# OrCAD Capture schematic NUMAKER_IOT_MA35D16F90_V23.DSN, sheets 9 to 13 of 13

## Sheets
9 03. PowerOn_SWJ(VDDIO1): size B; note: 03. Power On Setting (VDDIO1); block SCHEMATIC03
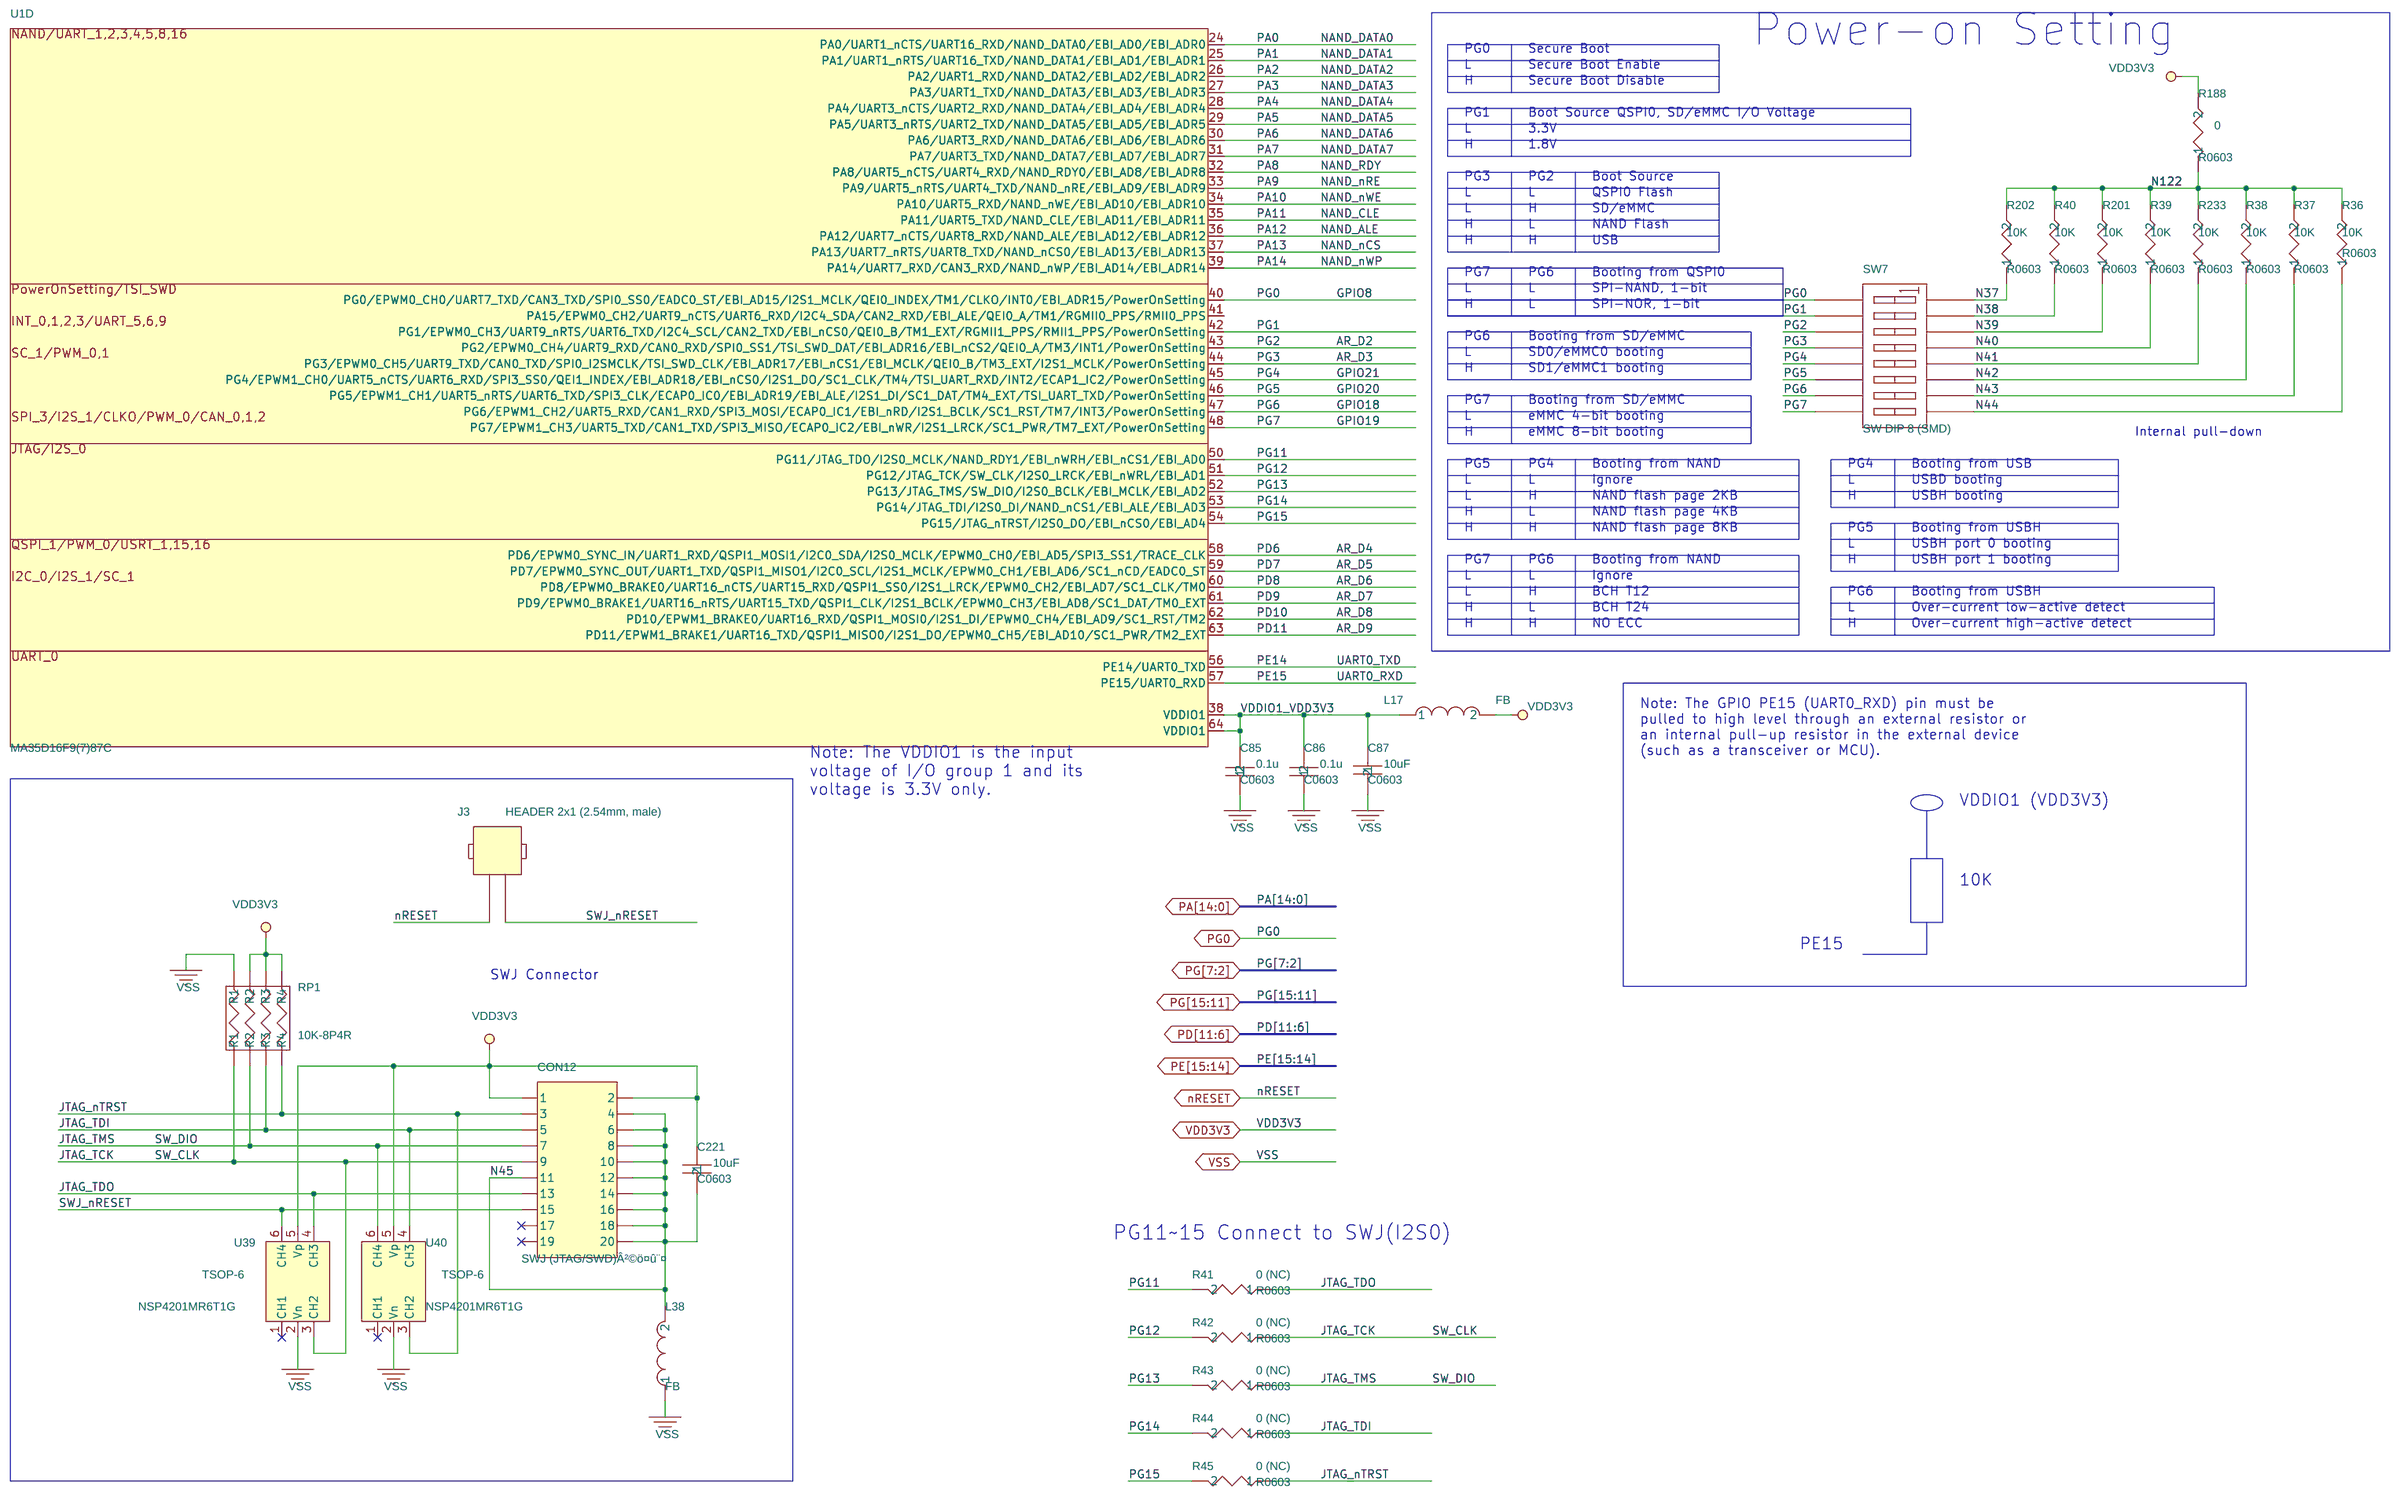
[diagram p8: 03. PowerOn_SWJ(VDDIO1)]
10 04. CCAP0 (VDDIO2): size B; note: 04. CCAP0 (VDDIO2); block SCHEMATIC04
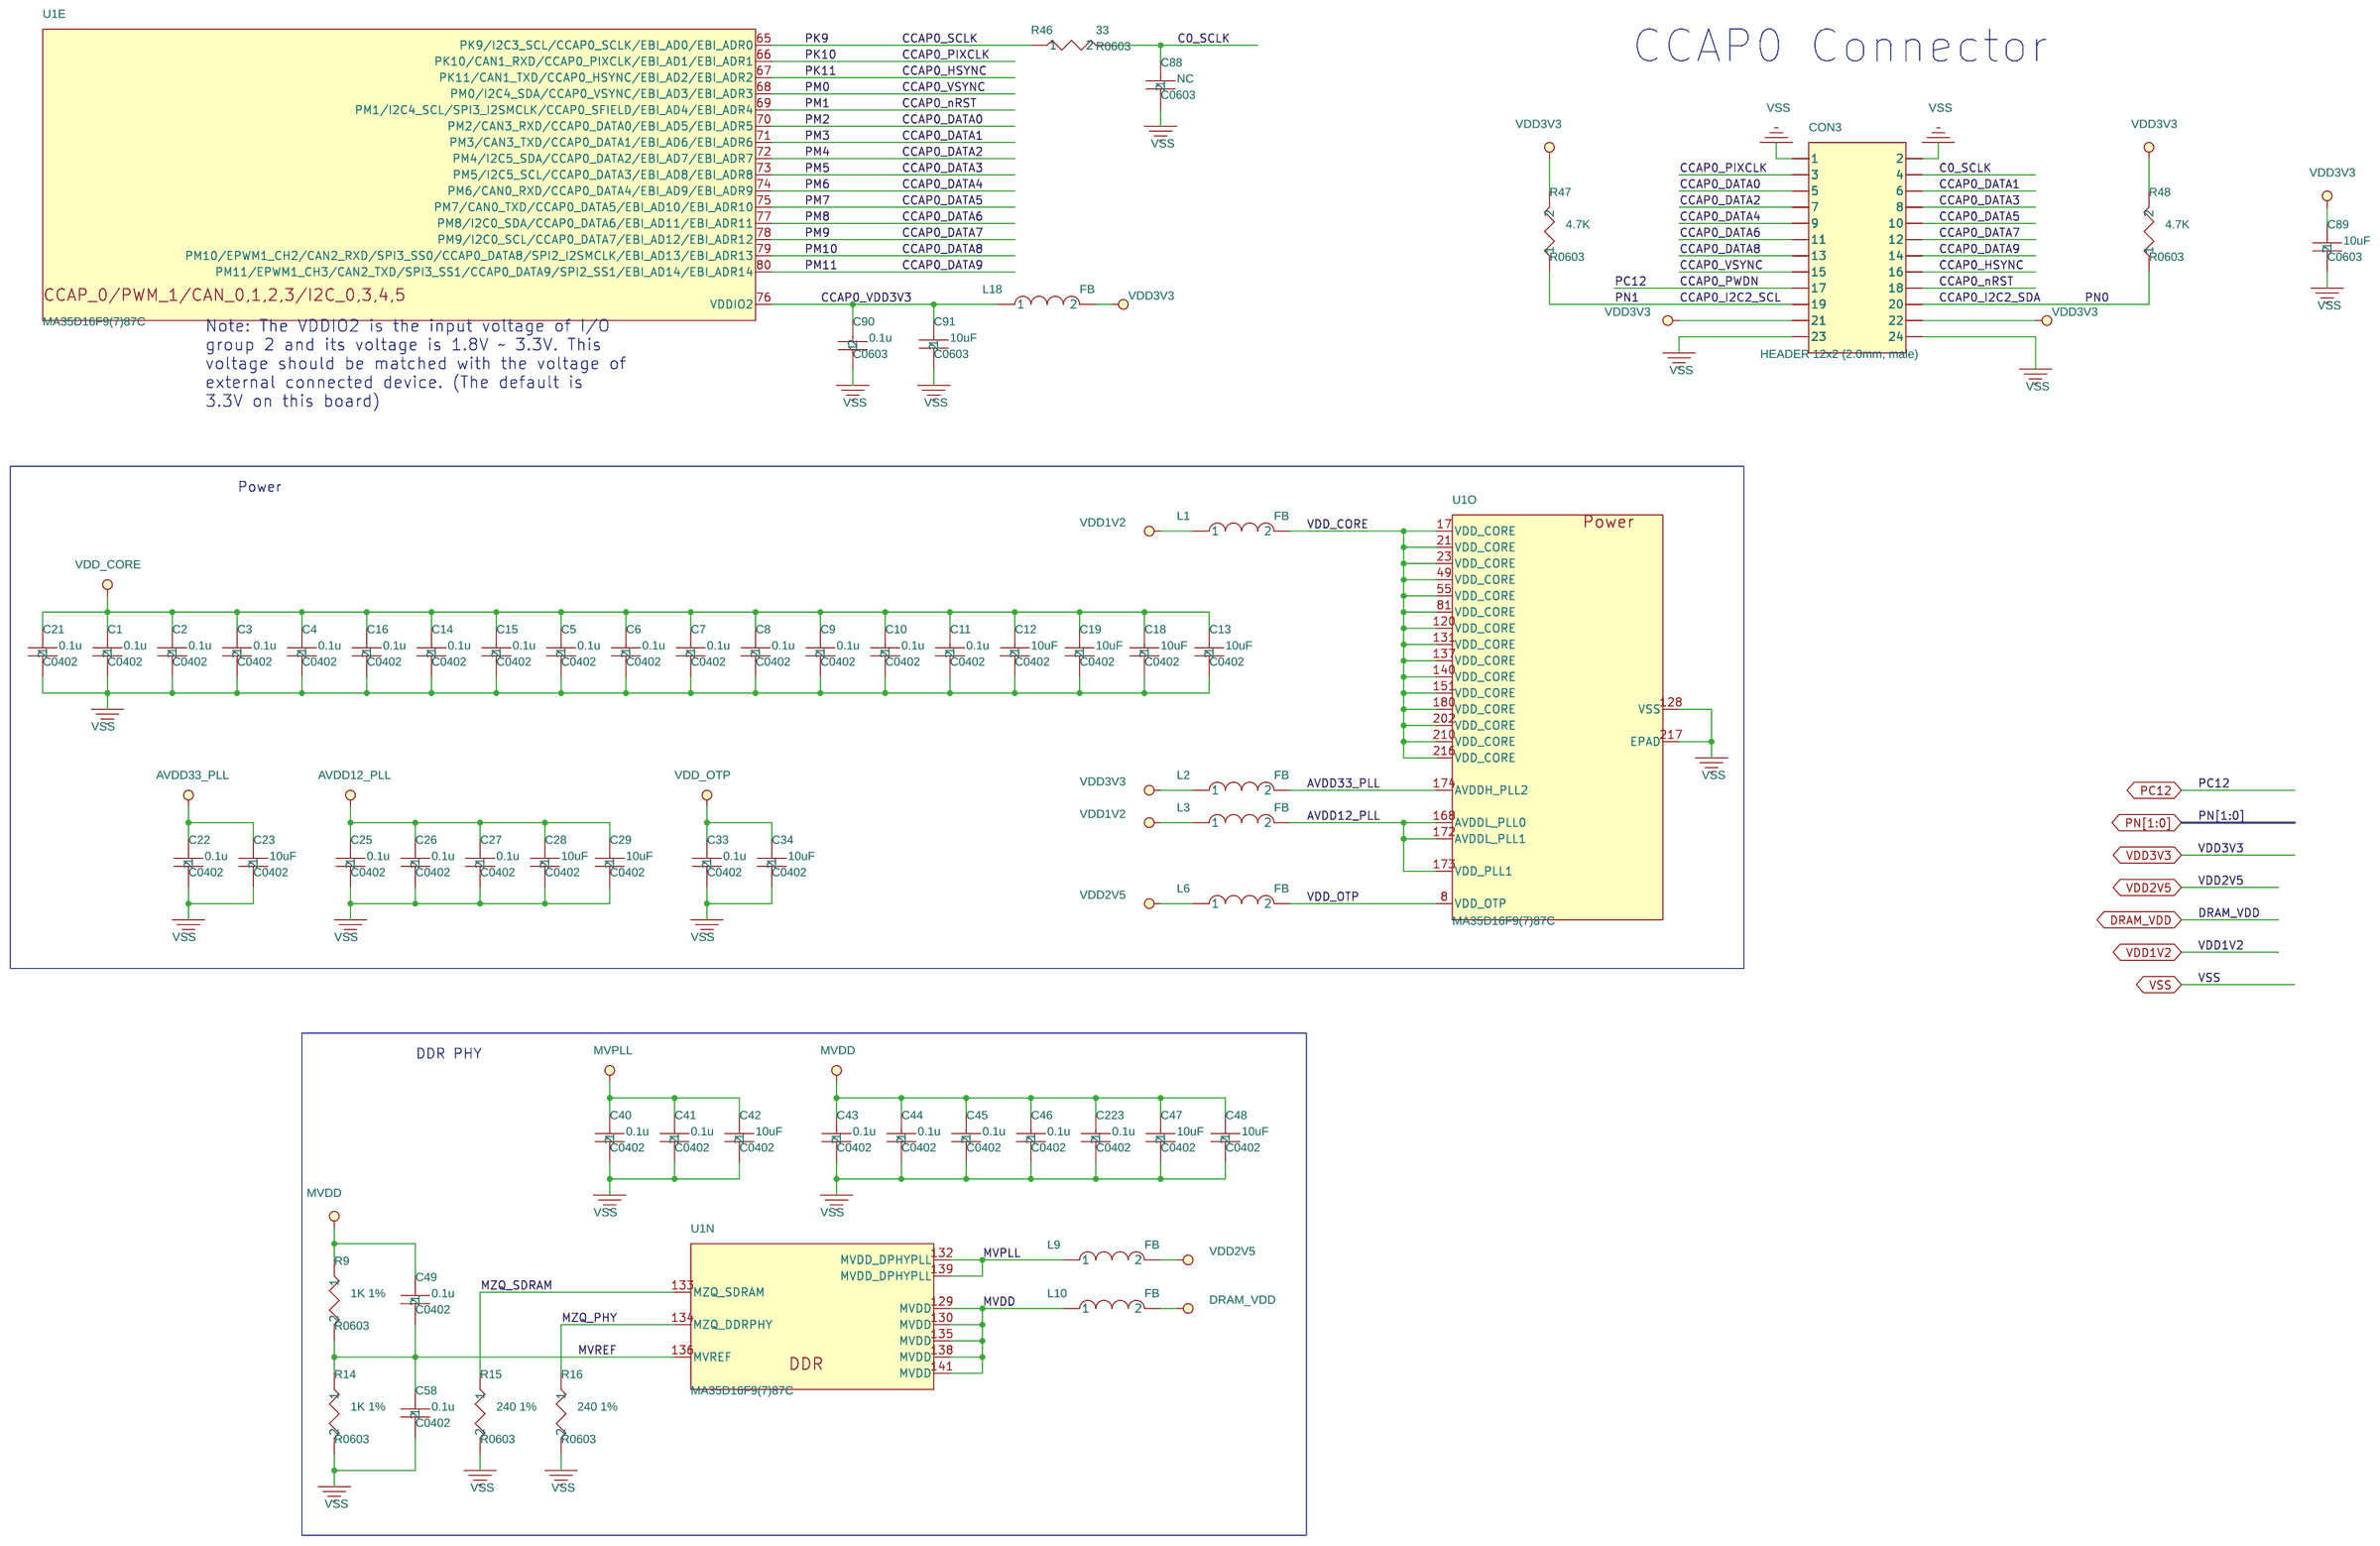
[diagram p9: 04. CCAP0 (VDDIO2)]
11 05. RP PI (VDDIO4): size B; note: 05. RP PI (VDDIO4); block SCHEMATIC05
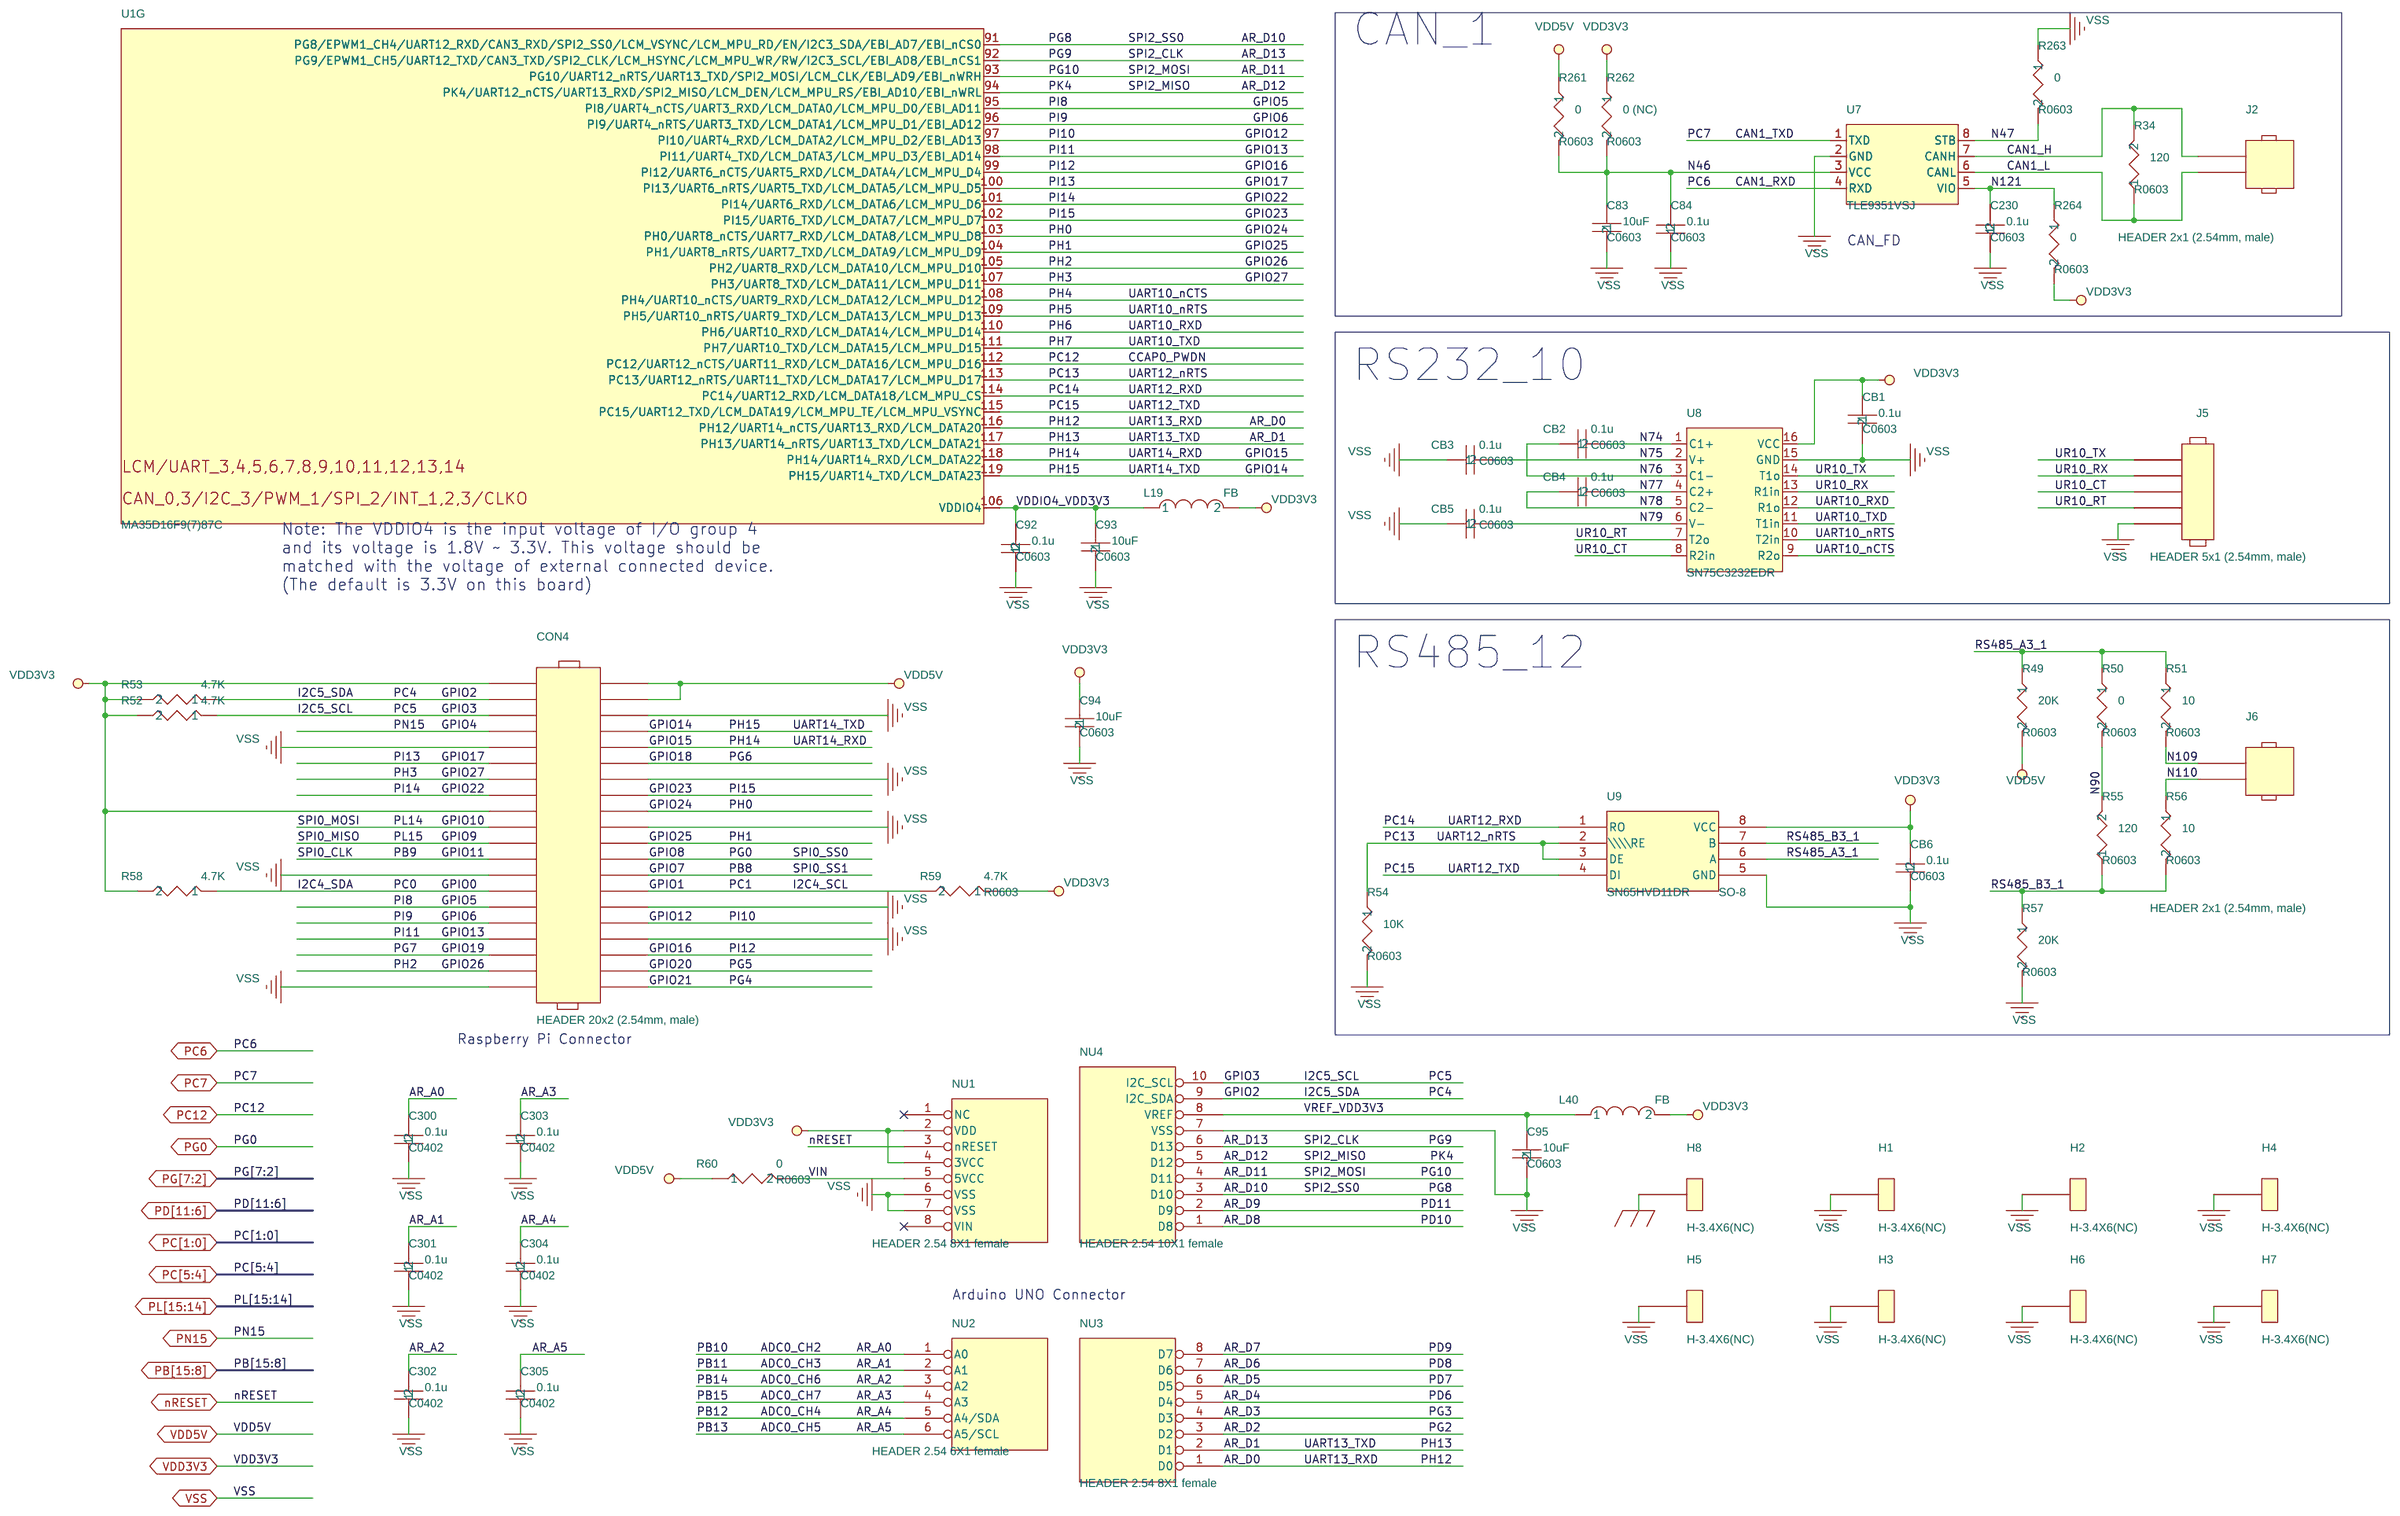
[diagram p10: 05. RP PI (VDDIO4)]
12 06. NAND/QSPI0 (VDDIO5): size B; note: 06. NAND/QSPI0 (VDDIO5); block SCHEMATIC06
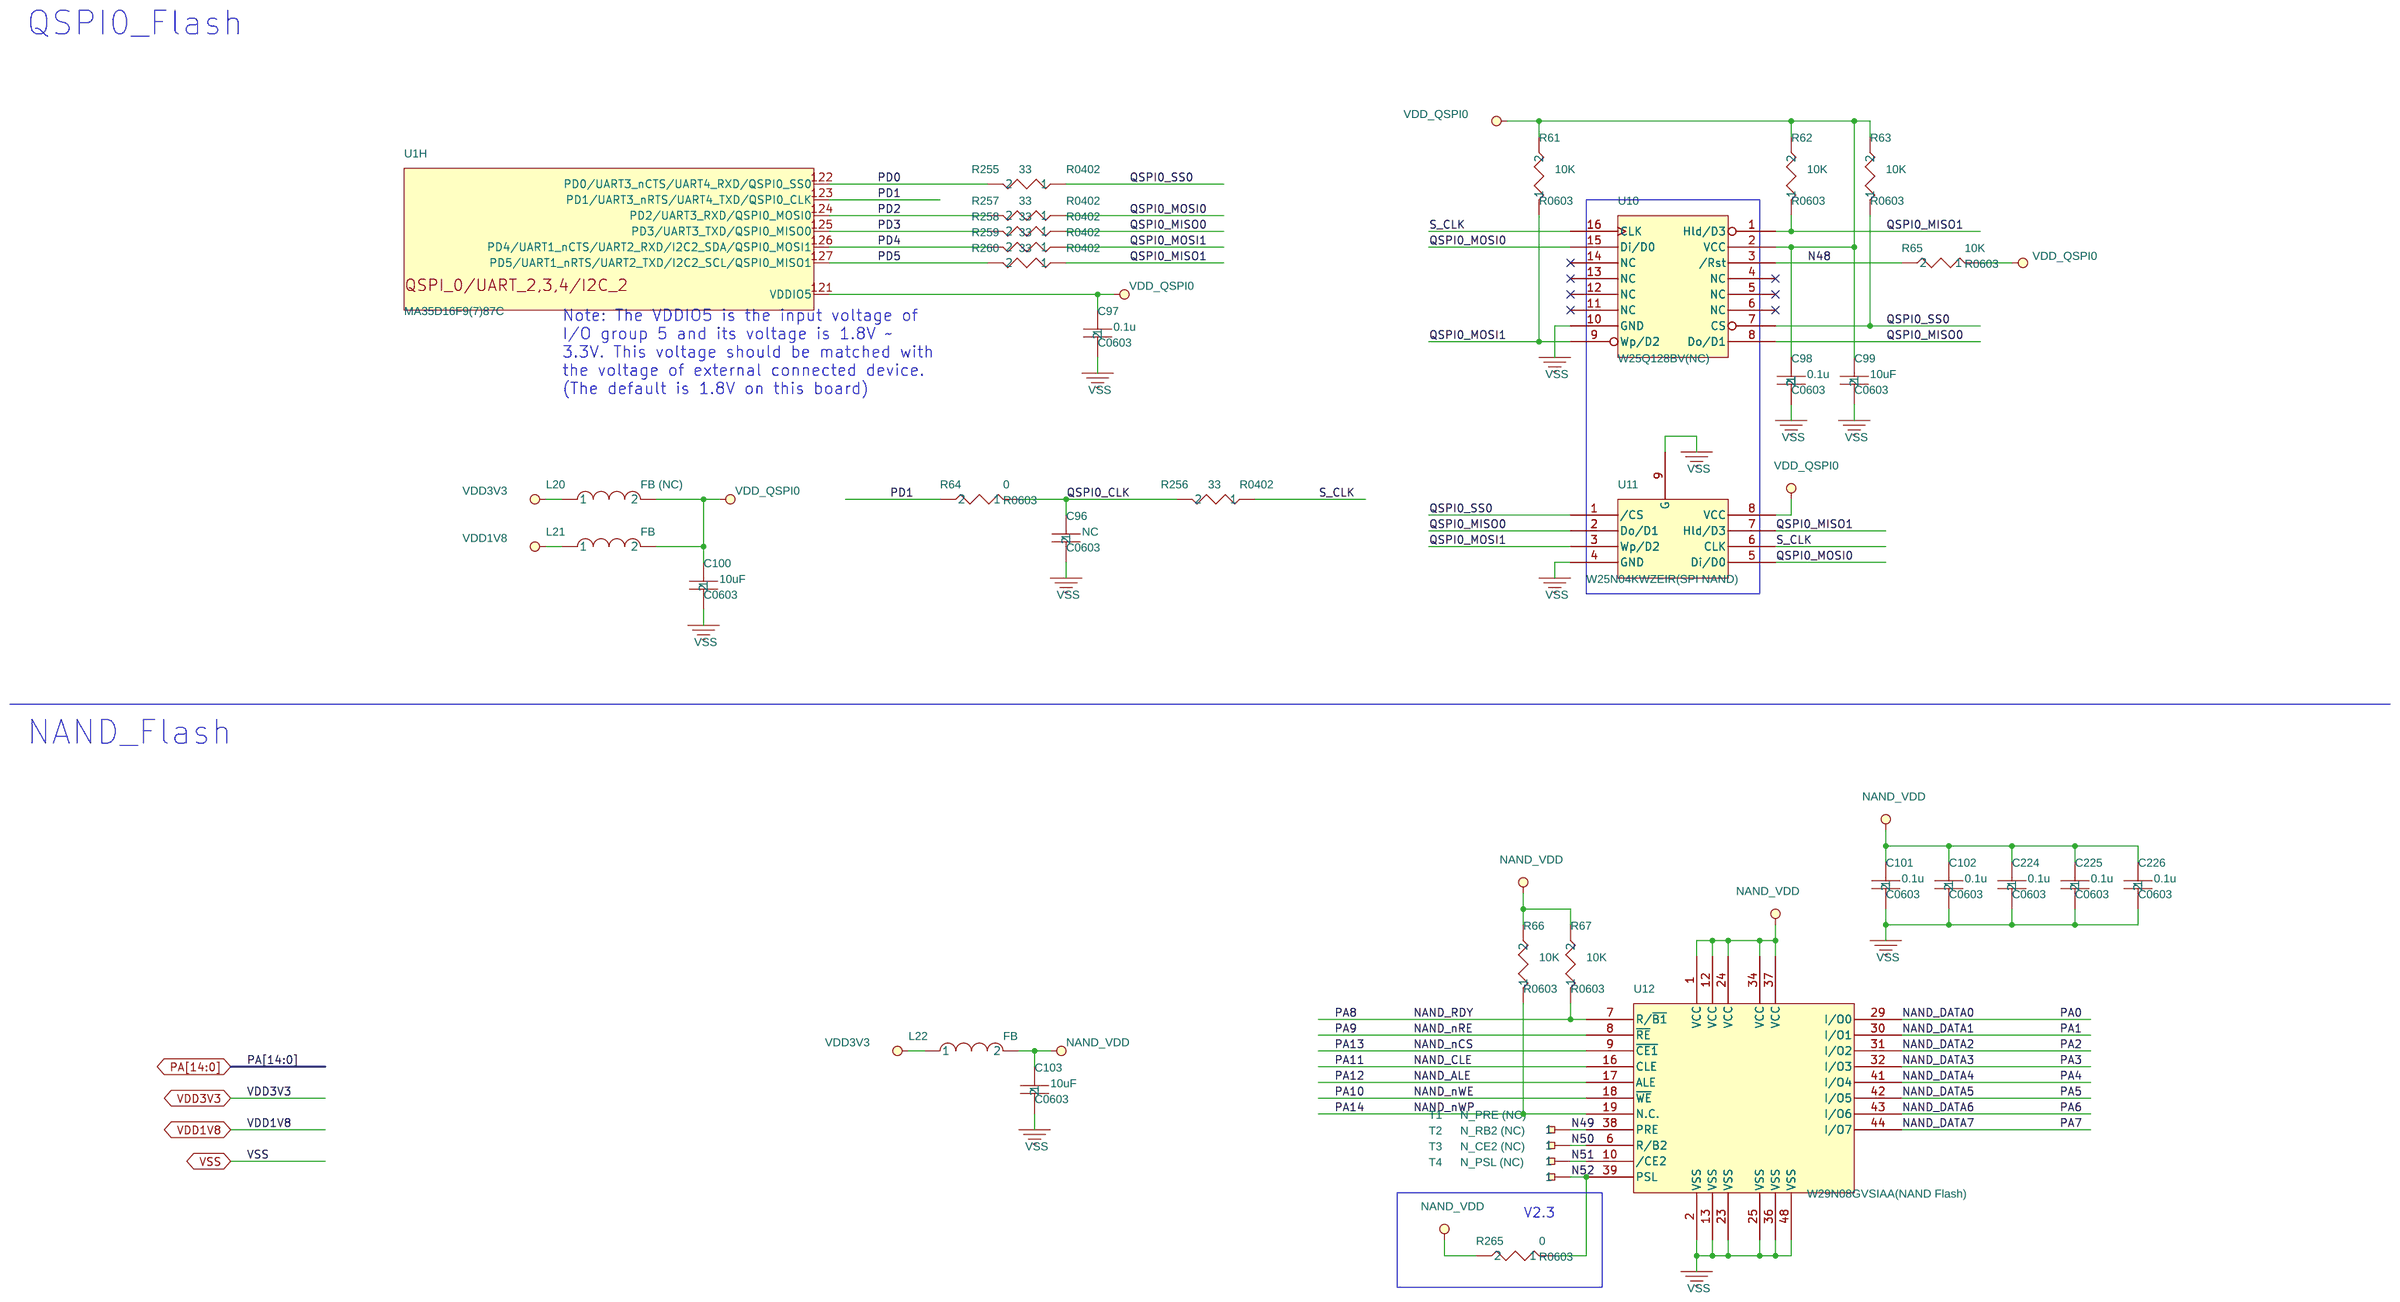
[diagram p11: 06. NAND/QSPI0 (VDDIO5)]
13 07. SD1 (VDDIO3): size B; note: 07. SD1 (VDDIO3); block SCHEMATIC07
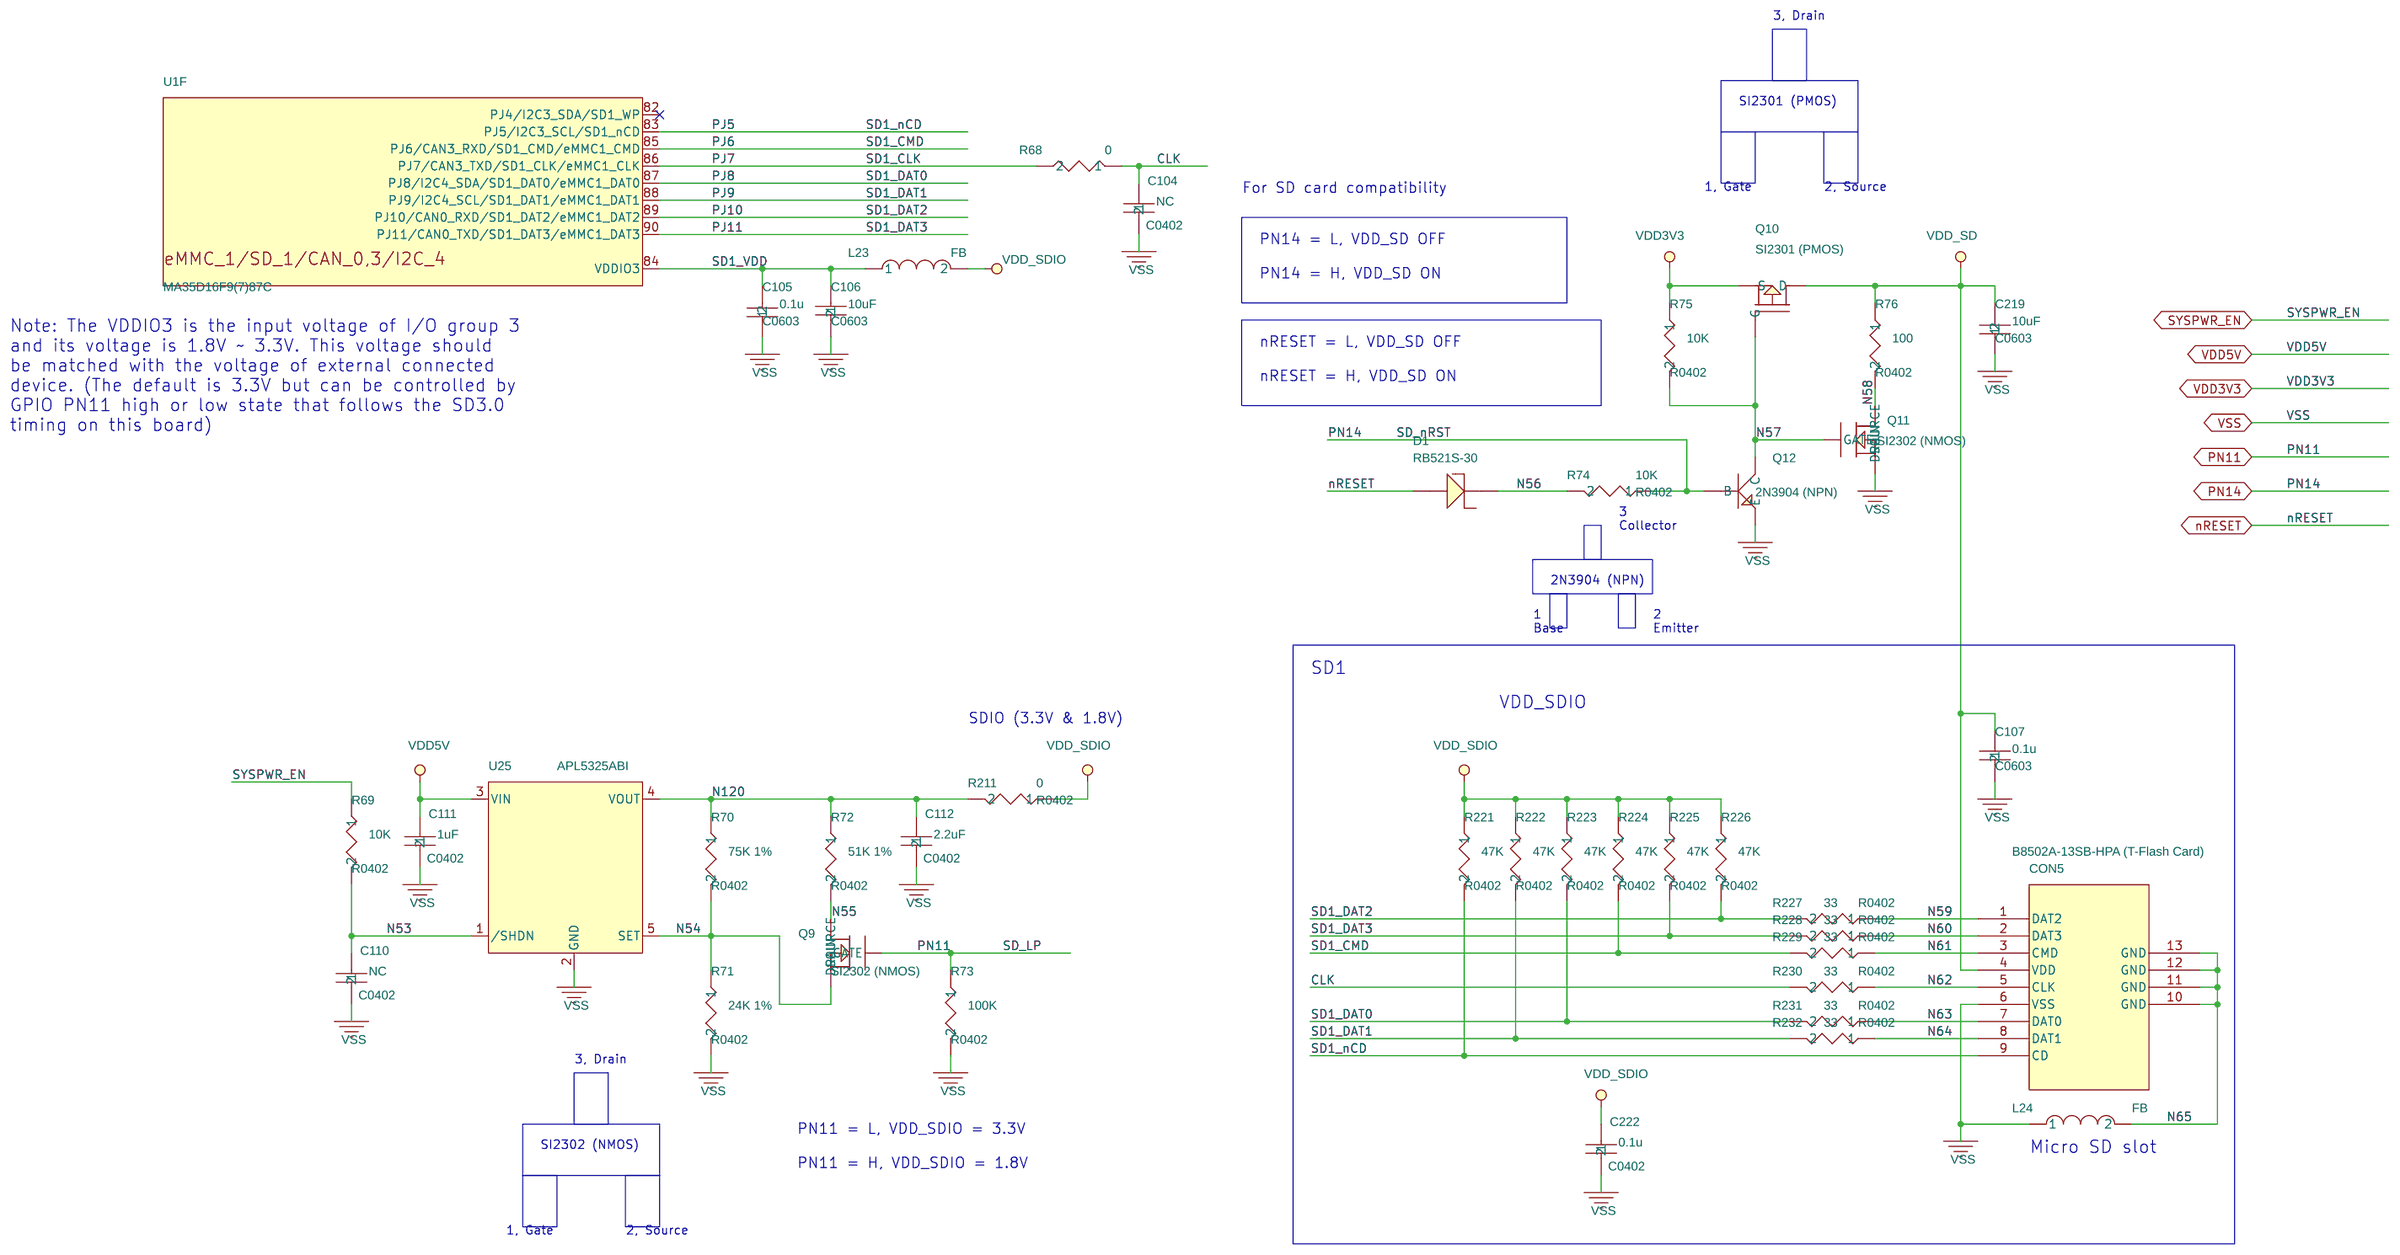
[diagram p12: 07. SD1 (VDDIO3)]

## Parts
sheet 03. PowerOn_SWJ(VDDIO1)
C85  0.1u  [C0603]
C86  0.1u  [C0603]
C87  10uF  [C0603]
C221  10uF  [C0603]
CON12  SWJ (JTAG/SWD)Â²©ö¤û¨¤  [HEADER10X2\BOX]
J3  HEADER 2x1 (2.54mm, male)  [HEADER2x1]
L17  FB  [L0603]
L38  FB  [L0603]
R36  10K  [R0603]
R37  10K  [R0603]
R38  10K  [R0603]
R39  10K  [R0603]
R40  10K  [R0603]
R41  0 (NC)  [R0603]
R42  0 (NC)  [R0603]
R43  0 (NC)  [R0603]
R44  0 (NC)  [R0603]
R45  0 (NC)  [R0603]
R188  0  [R0603]
R201  10K  [R0603]
R202  10K  [R0603]
R233  10K  [R0603]
RP1  10K-8P4R  [8P4RA]
SW7  SW DIP 8 (SMD)  [SWDIP-8/SMD]
U39  NSP4201MR6T1G  [TSOP-6]
U40  NSP4201MR6T1G  [TSOP-6]
sheet 04. CCAP0 (VDDIO2)
C1  0.1u  [C0402]
C2  0.1u  [C0402]
C3  0.1u  [C0402]
C4  0.1u  [C0402]
C5  0.1u  [C0402]
C6  0.1u  [C0402]
C7  0.1u  [C0402]
C8  0.1u  [C0402]
C9  0.1u  [C0402]
C10  0.1u  [C0402]
C11  0.1u  [C0402]
C12  10uF  [C0402]
C13  10uF  [C0402]
C14  0.1u  [C0402]
C15  0.1u  [C0402]
C16  0.1u  [C0402]
C18  10uF  [C0402]
C19  10uF  [C0402]
C21  0.1u  [C0402]
C22  0.1u  [C0402]
C23  10uF  [C0402]
C25  0.1u  [C0402]
C26  0.1u  [C0402]
C27  0.1u  [C0402]
C28  10uF  [C0402]
C29  10uF  [C0402]
C33  0.1u  [C0402]
C34  10uF  [C0402]
C40  0.1u  [C0402]
C41  0.1u  [C0402]
C42  10uF  [C0402]
C43  0.1u  [C0402]
C44  0.1u  [C0402]
C45  0.1u  [C0402]
C46  0.1u  [C0402]
C47  10uF  [C0402]
C48  10uF  [C0402]
C49  0.1u  [C0402]
C58  0.1u  [C0402]
C88  NC  [C0603]
C89  10uF  [C0603]
C90  0.1u  [C0603]
C91  10uF  [C0603]
C223  0.1u  [C0402]
CON3  HEADER 12x2 (2.0mm, male)  [HEADER12x2_2.0mm]
L1  FB  [L0603]
L2  FB  [L0603]
L3  FB  [L0603]
L6  FB  [L0603]
L9  FB  [L0603]
L10  FB  [L0603]
L18  FB  [L0603]
R9  1K 1%  [R0603]
R14  1K 1%  [R0603]
R15  240 1%  [R0603]
R16  240 1%  [R0603]
R46  33  [R0603]
R47  4.7K  [R0603]
R48  4.7K  [R0603]
sheet 05. RP PI (VDDIO4)
C83  10uF  [C0603]
C84  0.1u  [C0603]
C92  0.1u  [C0603]
C93  10uF  [C0603]
C94  10uF  [C0603]
C95  10uF  [C0603]
C230  0.1u  [C0603]
C300  0.1u  [C0402]
C301  0.1u  [C0402]
C302  0.1u  [C0402]
C303  0.1u  [C0402]
C304  0.1u  [C0402]
C305  0.1u  [C0402]
CB1  0.1u  [C0603]
CB2  0.1u  [C0603]
CB3  0.1u  [C0603]
CB4  0.1u  [C0603]
CB5  0.1u  [C0603]
CB6  0.1u  [C0603]
CON4  HEADER 20x2 (2.54mm, male)  [HEADER20X2/2.54MM_M]
H1  H-3.4X6(NC)  [H-3.4X6]
H2  H-3.4X6(NC)  [H-3.4X6]
H3  H-3.4X6(NC)  [H-3.4X6]
H4  H-3.4X6(NC)  [H-3.4X6]
H5  H-3.4X6(NC)  [H-3.4X6]
H6  H-3.4X6(NC)  [H-3.4X6]
H7  H-3.4X6(NC)  [H-3.4X6]
H8  H-3.4X6(NC)  [H-3.4X6]
J2  HEADER 2x1 (2.54mm, male)  [HEADER2x1]
J5  HEADER 5x1 (2.54mm, male)  [HEADER5x1]
J6  HEADER 2x1 (2.54mm, male)  [HEADER2x1]
L19  FB  [L0603]
L40  FB  [L0603]
NU1  HEADER 2.54 8X1 female  [SIP-8P]
NU2  HEADER 2.54 6X1 female  [SIP-6P]
NU3  HEADER 2.54 8X1 female  [SIP-8P]
NU4  HEADER 2.54 10X1 female  [SIP-10P]
R34  120  [R0603]
R49  20K  [R0603]
R50  0  [R0603]
R51  10  [R0603]
R52  4.7K  [R0603]
R53  4.7K  [R0603]
R54  10K  [R0603]
R55  120  [R0603]
R56  10  [R0603]
R57  20K  [R0603]
R58  4.7K  [R0603]
R59  4.7K  [R0603]
R60  0  [R0603]
R261  0  [R0603]
R262  0 (NC)  [R0603]
R263  0  [R0603]
R264  0  [R0603]
U7  TLE9351VSJ  [SOIC8]
U8  SN75C3232EDR  [SOP16/150]
U9  SN65HVD11DR  [SO-8]
sheet 06. NAND/QSPI0 (VDDIO5)
C96  NC  [C0603]
C97  0.1u  [C0603]
C98  0.1u  [C0603]
C99  10uF  [C0603]
C100  10uF  [C0603]
C101  0.1u  [C0603]
C102  0.1u  [C0603]
C103  10uF  [C0603]
C224  0.1u  [C0603]
C225  0.1u  [C0603]
C226  0.1u  [C0603]
L20  FB (NC)  [L0603]
L21  FB  [L0603]
L22  FB  [L0603]
R61  10K  [R0603]
R62  10K  [R0603]
R63  10K  [R0603]
R64  0  [R0603]
R65  10K  [R0603]
R66  10K  [R0603]
R67  10K  [R0603]
R255  33  [R0402]
R256  33  [R0402]
R257  33  [R0402]
R258  33  [R0402]
R259  33  [R0402]
R260  33  [R0402]
R265  0  [R0603]
T1  N_PRE (NC)  [1PAD_1.25x1.25mm]
T2  N_RB2 (NC)  [1PAD_1.25x1.25mm]
T3  N_CE2 (NC)  [1PAD_1.25x1.25mm]
T4  N_PSL (NC)  [1PAD_1.25x1.25mm]
U10  W25Q128BV(NC)  [SOIC16_300]
U11  W25N04KWZEIR(SPI NAND)  [SOIC8_208_EP]
U12  W29N08GVSIAA(NAND Flash)  [TSOP48-0.5mm]
sheet 07. SD1 (VDDIO3)
C104  NC  [C0402]
C105  0.1u  [C0603]
C106  10uF  [C0603]
C107  0.1u  [C0603]
C110  NC  [C0402]
C111  1uF  [C0402]
C112  2.2uF  [C0402]
C219  10uF  [C0603]
C222  0.1u  [C0402]
CON5  B8502A-13SB-HPA (T-Flash Card)  [B8502A-13SB-HPA]
D1  RB521S-30  [SOD-523]
L23  FB  [L0603]
L24  FB  [L0603]
Q9  SI2302 (NMOS)  [SOT-23]
Q10  SI2301 (PMOS)  [SOT-23]
Q11  SI2302 (NMOS)  [SOT-23]
Q12  2N3904 (NPN)  [SOT-23]
R68  0  [R0603]
R69  10K  [R0402]
R70  75K 1%  [R0402]
R71  24K 1%  [R0402]
R72  51K 1%  [R0402]
R73  100K  [R0402]
R74  10K  [R0402]
R75  10K  [R0402]
R76  100  [R0402]
R211  0  [R0402]
R221  47K  [R0402]
R222  47K  [R0402]
R223  47K  [R0402]
R224  47K  [R0402]
R225  47K  [R0402]
R226  47K  [R0402]
R227  33  [R0402]
R228  33  [R0402]
R229  33  [R0402]
R230  33  [R0402]
R231  33  [R0402]
R232  33  [R0402]
U25  APL5325ABI  [SOT-23-5]
sheet 08.RGMII0_RTL8211F(D)I (VDDIO8)
U1  MA35D16F9(7)87C  [LQFP216]  (sections A,B,C,D,E,F,G,H,I,J,K,L,M,N,O)

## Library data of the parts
C85 C219 C226 CB2 = CAP-C_3: Package: 0603
C86 C100 C107 CB3 = CAP-C: Package: 0603
C83 C87 C98 = CAP-C_2: Package: 0603
C95 C99 C221 = CAP-C_1: Package: 0603
CON12 = HEADER_2X20_0: Package: HEADER10X2
J2 J3 J6 = HEADER_2
L17 L18 L22 L23 L40 = INDUCTOR
L2 L19 L20 L24 L38 = INDUCTOR_1
R36 R64 R225 R263 = R_0_12: Package: 0603
R37 R51 R224 R258 = R_0_13: Package: 0603
R38 R48 R57 R73 R265 = R_0: Package: 0603
R14 R39 R59 R62 R76 = R_0_5: Package: 0603
R40 R50 R65 R227 = R_0_9: Package: 0603
R41 R47 R63 R228 R261 = R_0_3: Package: 0603
R42 R70 R259 R264 = R_0_11: Package: 0603
R15 R34 R43 R72 R255 = R_0_4: Package: 0603
R9 R44 R56 R61 R69 = R_0_6: Package: 0603
R45 R46 R231 R257 R262 = R_0_1: Package: 0603
R60 R66 R188 R226 = R_0_10: Package: 0603
R55 R67 R75 R201 = R_0_7: Package: 0603
R49 R202 R229 R260 = R_0_8: Package: 0603
R16 R54 R71 R233 R256 = R_0_2: Package: 0603
RP1 = R-PACK8_0
SW7 = SW_DIP-7_1
U39 U40 = PJ9293_0
C1 C301 = CAP-C_18: Package: 0402
C2 C300 = CAP-C_14: Package: 0402
C3 C110 = CAP-C_8: Package: 0402
C4 C222 C305 = CAP-C_4: Package: 0402
C5 = CAP-C_24: Package: 0402
C6 = CAP-C_3: Package: 0402
C7 = CAP-C_23: Package: 0402
C8 C303 = CAP-C_7: Package: 0402
C9 C104 = CAP-C_2: Package: 0402
C10 = CAP-C_29: Package: 0402
C11 = CAP-C_10: Package: 0402
C12 = CAP-C_33: Package: 0402
C13 = CAP-C_15: Package: 0402
C14 = CAP-C_38: Package: 0402
C15 = CAP-C_31: Package: 0402
C16 = CAP-C_41: Package: 0402
C18 = CAP-C_35: Package: 0402
C19 = CAP-C_12: Package: 0402
C21 = CAP-C_37: Package: 0402
C22 = CAP-C_21: Package: 0402
C23 C111 = CAP-C_1: Package: 0402
C25 = CAP-C_40: Package: 0402
C26 = CAP-C_11: Package: 0402
C27 = CAP-C_30: Package: 0402
C28 = CAP-C_34: Package: 0402
C29 = CAP-C_13: Package: 0402
C33 = CAP-C_39: Package: 0402
C34 = CAP-C_16: Package: 0402
C40 = CAP-C_28: Package: 0402
C41 = CAP-C_9: Package: 0402
C42 = CAP-C_32: Package: 0402
C43 = CAP-C_43: Package: 0402
C44 = CAP-C_20: Package: 0402
C45 = CAP-C: Package: 0402
C46 C112 C302 = CAP-C_5: Package: 0402
C47 = CAP-C_25: Package: 0402
C48 C304 = CAP-C_6: Package: 0402
C49 = CAP-C_36: Package: 0402
C58 = CAP-C_26: Package: 0402
C88 C92 = CAP-C_17: Package: 0603
C89 = CAP-C_27: Package: 0603
C90 = CAP-C_42: Package: 0603
C91 = CAP-C_19: Package: 0603
C223 = CAP-C_22: Package: 0402
CON3 = CON24A
L1 = INDUCTOR_5
L3 = INDUCTOR_6
L6 = INDUCTOR_4
L9 = INDUCTOR_3
L10 L21 = INDUCTOR_2
C84 = CAP-C_16: Package: 0603
C93 C101 = CAP-C_8: Package: 0603
C94 = CAP-C_13: Package: 0603
C230 = CAP-C_15: Package: 0603
CB1 = CAP-C_11: Package: 0603
CB4 = CAP-C_12: Package: 0603
C96 CB5 = CAP-C_9: Package: 0603
C103 CB6 = CAP-C_10: Package: 0603
CON4 = HEADER_20X2
H1-H8 = TEST_POINT
J5 = HEADER_5
NU1 = POWER_CONNECT_0
NU2 = ADC_CONNECT_0
NU3 = PWM0_CONNECT_0
NU4 = PWM1_CONNECT_1
R52 R68 = R
R53 = R_1
R58 = R_2
U7 = TCAN332GD_0
U8 = ADM232_0
U9 = ADM232_1: Package: DIP16\SO
C97 C105 = CAP-C_7: Package: 0603
C102 C106 = CAP-C_6: Package: 0603
C224 = CAP-C_5: Package: 0603
C225 = CAP-C_4: Package: 0603
T1-T4 = 1PAD_1
U10 = W25Q128BV_4
U11 = W55X10_3
U12 = NAND_4-8G_4
CON5 = B8502A-13SB-HPA_(T-Flash_Card)
D1 = ZENAR_0: Package: D
Q9 Q11 = MOSFET_N_4
Q10 = MOSFET_P_4
Q12 = PNP_0
R74 = R_0_15: Package: 0603
R211 = R_0_19: Package: 0603
R221 = R_0_20: Package: 0603
R222 = R_0_17: Package: 0603
R223 = R_0_18: Package: 0603
R230 = R_0_14: Package: 0603
R232 = R_0_16: Package: 0603
U25 = APL5325BI
U1 = MA35D1_LQFP216

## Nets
AVDD12_PLL: C25.1 C26.1 C27.1 C28.1 C29.1 L3.2 U1.168(AVDDL_PLL0) U1.172(AVDDL_PLL1) U1.173(VDD_PLL1)
AVDD33_PLL: C22.1 C23.1 L2.2 U1.174(AVDDH_PLL2)
GND_EARTH: H8.1 ; also on sheet 2 3
SCHEMATIC03/VDDIO1_VDD3V3: C85.2 C86.2 C87.1 L17.1 U1.38(VDDIO1) U1.64(VDDIO1)
SCHEMATIC05/VDDIO4_VDD3V3: C92.2 C93.1 L19.1 U1.106(VDDIO4)
SCHEMATIC05/VIN: NU1.5(5VCC) R60.2
VDD1V2: L1.1 L3.1 ; also on sheet 7 8
VDD1V8: L21.1 ; also on sheet 2 7
VDD2V5: L6.1 L9.2 ; also on sheet 7
VDD3V3: C89.1 C94.1 C221.1 CB1.1 CB6.2 CON3.21 CON3.22 CON4.1 CON4.17 CON12.1 CON12.2 L2.1 L17.2 L18.2 L19.2 L20.1 L22.1 L40.2 NU1.2(VDD) NU1.4(3VCC) Q10.2(S) R47.2 R48.2 R52.2 R53.2 R58.2 R59.1 R75.1 R188.2 R262.1 R264.2 RP1.4(R2) RP1.6(R3) RP1.8(R4) U8.16(VCC) U9.8(VCC) U39.5(Vp) U40.5(Vp) ; also on sheet 2 3 4 5 6 7 8
VDD5V: C111.1 CON4.2 CON4.4 R49.2 R60.1 R261.1 U25.3(VIN) ; also on sheet 6 7
VDD_CORE: C1.1 C2.1 C3.1 C4.1 C5.1 C6.1 C7.1 C8.1 C9.1 C10.1 C11.1 C12.1 C13.1 C14.1 C15.1 C16.1 C18.1 C19.1 C21.1 L1.2 U1.17(VDD_CORE) U1.21(VDD_CORE) U1.23(VDD_CORE) U1.49(VDD_CORE) U1.55(VDD_CORE) U1.81(VDD_CORE) U1.120(VDD_CORE) U1.131(VDD_CORE) U1.137(VDD_CORE) U1.140(VDD_CORE) U1.151(VDD_CORE) U1.180(VDD_CORE) U1.202(VDD_CORE) U1.210(VDD_CORE) U1.216(VDD_CORE)
VDD_OTP: C33.1 C34.1 L6.2 U1.8(VDD_OTP)
VDD_QSPI0: C97.1 C98.1 C99.1 C100.1 L20.2 L21.2 R61.2 R62.2 R63.2 R65.1 U1.121(VDDIO5) U10.2(VCC) U11.8(VCC)
VDD_SD: C107.1 C219.2 CON5.4(VDD) Q10.3(D) R76.1
VDD_SDIO: C222.1 L23.2 R211.1 R221.1 R222.1 R223.1 R224.1 R225.1 R226.1
VSS: C1.2 C2.2 C3.2 C4.2 C5.2 C6.2 C7.2 C8.2 C9.2 C10.2 C11.2 C12.2 C13.2 C14.2 C15.2 C16.2 C18.2 C19.2 C21.2 C22.2 C23.2 C25.2 C26.2 C27.2 C28.2 C29.2 C33.2 C34.2 C40.2 C41.2 C42.2 C43.2 C44.2 C45.2 C46.2 C47.2 C48.2 C58.2 C83.2 C84.1 C85.1 C86.1 C87.2 C88.2 C89.2 C90.1 C91.2 C92.1 C93.2 C94.2 C95.2 C96.2 C97.2 C98.2 C99.2 C100.2 C101.2 C102.2 C103.2 C104.2 C105.1 C106.2 C107.2 C110.2 C111.2 C112.2 C219.1 C222.2 C223.2 C224.2 C225.2 C226.2 C230.1 C300.1 C301.1 C302.1 C303.1 C304.1 C305.1 CB1.2 CB3.1 CB5.1 CB6.1 CON3.1 CON3.2 CON3.23 CON3.24 CON4.6 CON4.9 CON4.14 CON4.20 CON4.25 CON4.30 CON4.34 CON4.39 CON5.6(VSS) H1.1 H2.1 H3.1 H4.1 H5.1 H6.1 H7.1 J5.5 L24.1 L38.1 NU1.6(VSS) NU1.7(VSS) NU4.7(VSS) Q11.2(SOURCE) Q12.2(E) R14.2 R15.2 R16.2 R54.2 R57.2 R71.2 R73.2 R263.1 RP1.2(R1) U1.128(VSS) U1.217(EPAD) U7.2(GND) U8.15(GND) U9.5(GND) U10.10(GND) U11.4(GND) U11.9(G) U12.2(VSS) U12.13(VSS) U12.23(VSS) U12.25(VSS) U12.36(VSS) U12.48(VSS) U25.2(GND) U39.2(Vn) U40.2(Vn) ; also on sheet 2 3 4 5 6 7 8
DRAM_VDD: L10.2 ; also on sheet 7
MVDD: C43.1 C44.1 C45.1 C46.1 C47.1 C48.1 C49.1 C223.1 L10.1 R9.1 U1.129(MVDD) U1.130(MVDD) U1.135(MVDD) U1.138(MVDD) U1.141(MVDD)
MVPLL: C40.1 C41.1 C42.1 L9.1 U1.132(MVDD_DPHYPLL) U1.139(MVDD_DPHYPLL)
NAND_VDD: C101.1 C102.1 C103.1 C224.1 C225.1 C226.1 L22.2 R66.2 R67.2 R265.2 U12.1(VCC) U12.12(VCC) U12.24(VCC) U12.34(VCC) U12.37(VCC)
nRESET: D1.1 J3.1 NU1.3(nRESET) ; also on sheet 2 3 8
PA0: U1.24(PA0/UART1_nCTS/UART16_RXD/NAND_DATA0/EBI_AD0/EBI_ADR0) U12.29(I/O0)
PA1: U1.25(PA1/UART1_nRTS/UART16_TXD/NAND_DATA1/EBI_AD1/EBI_ADR1) U12.30(I/O1)
PA2: U1.26(PA2/UART1_RXD/NAND_DATA2/EBI_AD2/EBI_ADR2) U12.31(I/O2)
PA3: U1.27(PA3/UART1_TXD/NAND_DATA3/EBI_AD3/EBI_ADR3) U12.32(I/O3)
PA4: U1.28(PA4/UART3_nCTS/UART2_RXD/NAND_DATA4/EBI_AD4/EBI_ADR4) U12.41(I/O4)
PA5: U1.29(PA5/UART3_nRTS/UART2_TXD/NAND_DATA5/EBI_AD5/EBI_ADR5) U12.42(I/O5)
PA6: U1.30(PA6/UART3_RXD/NAND_DATA6/EBI_AD6/EBI_ADR6) U12.43(I/O6)
PA7: U1.31(PA7/UART3_TXD/NAND_DATA7/EBI_AD7/EBI_ADR7) U12.44(I/O7)
PA8: R67.1 U1.32(PA8/UART5_nCTS/UART4_RXD/NAND_RDY0/EBI_AD8/EBI_ADR8) U12.7(R/~{B1})
PA9: U1.33(PA9/UART5_nRTS/UART4_TXD/NAND_nRE/EBI_AD9/EBI_ADR9) U12.8(~{RE})
PA10: U1.34(PA10/UART5_RXD/NAND_nWE/EBI_AD10/EBI_ADR10) U12.18(~{WE})
PA11: U1.35(PA11/UART5_TXD/NAND_CLE/EBI_AD11/EBI_ADR11) U12.16(CLE)
PA12: U1.36(PA12/UART7_nCTS/UART8_RXD/NAND_ALE/EBI_AD12/EBI_ADR12) U12.17(ALE)
PA13: U1.37(PA13/UART7_nRTS/UART8_TXD/NAND_nCS0/EBI_AD13/EBI_ADR13) U12.9(~{CE1})
PA14: R66.1 U1.39(PA14/UART7_RXD/CAN3_RXD/NAND_nWP/EBI_AD14/EBI_ADR14) U12.19(N.C.)
PB8: CON4.26 ; also on sheet 8
PB9: CON4.23 ; also on sheet 8
PB10: C300.2 NU2.1(A0) ; also on sheet 8
PB11: C301.2 NU2.2(A1) ; also on sheet 8
PB12: C304.2 NU2.5(A4/SDA) ; also on sheet 8
PB13: C305.2 NU2.6(A5/SCL) ; also on sheet 8
PB14: C302.2 NU2.3(A2) ; also on sheet 8
PB15: C303.2 NU2.4(A3) ; also on sheet 8
PC0: CON4.27 R58.1 ; also on sheet 8
PC1: CON4.28 R59.2 ; also on sheet 8
PC4: CON4.3 NU4.9(I2C_SDA) R53.1 ; also on sheet 8
PC5: CON4.5 NU4.10(I2C_SCL) R52.1 ; also on sheet 8
PC6: U7.4(RXD) ; also on sheet 8
PC7: U7.1(TXD) ; also on sheet 8
PC12: CON3.17 U1.112(PC12/UART12_nCTS/UART11_RXD/LCM_DATA16/LCM_MPU_D16)
PD6: NU3.5(D4) U1.58(PD6/EPWM0_SYNC_IN/UART1_RXD/QSPI1_MOSI1/I2C0_SDA/I2S0_MCLK/EPWM0_CH0/EBI_AD5/SPI3_SS1/TRACE_CLK)
PD7: NU3.6(D5) U1.59(PD7/EPWM0_SYNC_OUT/UART1_TXD/QSPI1_MISO1/I2C0_SCL/I2S1_MCLK/EPWM0_CH1/EBI_AD6/SC1_nCD/EADC0_ST)
PD8: NU3.7(D6) U1.60(PD8/EPWM0_BRAKE0/UART16_nCTS/UART15_RXD/QSPI1_SS0/I2S1_LRCK/EPWM0_CH2/EBI_AD7/SC1_CLK/TM0)
PD9: NU3.8(D7) U1.61(PD9/EPWM0_BRAKE1/UART16_nRTS/UART15_TXD/QSPI1_CLK/I2S1_BCLK/EPWM0_CH3/EBI_AD8/SC1_DAT/TM0_EXT)
PD10: NU4.1(D8) U1.62(PD10/EPWM1_BRAKE0/UART16_RXD/QSPI1_MOSI0/I2S1_DI/EPWM0_CH4/EBI_AD9/SC1_RST/TM2)
PD11: NU4.2(D9) U1.63(PD11/EPWM1_BRAKE1/UART16_TXD/QSPI1_MISO0/I2S1_DO/EPWM0_CH5/EBI_AD10/SC1_PWR/TM2_EXT)
PE14: U1.56(PE14/UART0_TXD) ; also on sheet 5
PE15: U1.57(PE15/UART0_RXD) ; also on sheet 5
PG0: CON4.24 SW7.1(A1) U1.40(PG0/EPWM0_CH0/UART7_TXD/CAN3_TXD/SPI0_SS0/EADC0_ST/EBI_AD15/I2S1_MCLK/QEI0_INDEX/TM1/CLKO/INT0/EBI_ADR15/PowerOnSetting)
PG2: NU3.3(D2) SW7.3(A3) U1.43(PG2/EPWM0_CH4/UART9_RXD/CAN0_RXD/SPI0_SS1/TSI_SWD_DAT/EBI_ADR16/EBI_nCS2/QEI0_A/TM3/INT1/PowerOnSetting)
PG3: NU3.4(D3) SW7.4(A4) U1.44(PG3/EPWM0_CH5/UART9_TXD/CAN0_TXD/SPI0_I2SMCLK/TSI_SWD_CLK/EBI_ADR17/EBI_nCS1/EBI_MCLK/QEI0_B/TM3_EXT/I2S1_MCLK/PowerOnSetting)
PG4: CON4.40 SW7.5(A5) U1.45(PG4/EPWM1_CH0/UART5_nCTS/UART6_RXD/SPI3_SS0/QEI1_INDEX/EBI_ADR18/EBI_nCS0/I2S1_DO/SC1_CLK/TM4/TSI_UART_RXD/INT2/ECAP1_IC2/PowerOnSetting)
PG5: CON4.38 SW7.6(A6) U1.46(PG5/EPWM1_CH1/UART5_nRTS/UART6_TXD/SPI3_CLK/ECAP0_IC0/EBI_ADR19/EBI_ALE/I2S1_DI/SC1_DAT/TM4_EXT/TSI_UART_TXD/PowerOnSetting)
PG6: CON4.12 SW7.7(A7) U1.47(PG6/EPWM1_CH2/UART5_RXD/CAN1_RXD/SPI3_MOSI/ECAP0_IC1/EBI_nRD/I2S1_BCLK/SC1_RST/TM7/INT3/PowerOnSetting)
PG7: CON4.35 SW7.8(A8) U1.48(PG7/EPWM1_CH3/UART5_TXD/CAN1_TXD/SPI3_MISO/ECAP0_IC2/EBI_nWR/I2S1_LRCK/SC1_PWR/TM7_EXT/PowerOnSetting)
PG11: R41.2 U1.50(PG11/JTAG_TDO/I2S0_MCLK/NAND_RDY1/EBI_nWRH/EBI_nCS1/EBI_AD0) ; also on sheet 4
PG12: R42.2 U1.51(PG12/JTAG_TCK/SW_CLK/I2S0_LRCK/EBI_nWRL/EBI_AD1) ; also on sheet 4
PG13: R43.2 U1.52(PG13/JTAG_TMS/SW_DIO/I2S0_BCLK/EBI_MCLK/EBI_AD2) ; also on sheet 4
PG14: R44.2 U1.53(PG14/JTAG_TDI/I2S0_DI/NAND_nCS1/EBI_ALE/EBI_AD3) ; also on sheet 4
PG15: R45.2 U1.54(PG15/JTAG_nTRST/I2S0_DO/EBI_nCS0/EBI_AD4) ; also on sheet 4
PL14: CON4.19 ; also on sheet 8
PL15: CON4.21 ; also on sheet 8
PN0: CON3.20 R48.1 ; also on sheet 8
PN1: CON3.19 R47.1 ; also on sheet 8
PN11: Q9.1(GATE) R73.1 ; also on sheet 8
PN14: Q12.1(B) R74.1 ; also on sheet 8
PN15: CON4.7 ; also on sheet 8
SCHEMATIC03/JTAG_nTRST: CON12.3 R45.1 RP1.7(R4) U40.3(CH2)
SCHEMATIC03/JTAG_TCK: CON12.9 R42.1 RP1.1(R1) U39.3(CH2)
SCHEMATIC03/JTAG_TDI: CON12.5 R44.1 RP1.5(R3) U40.4(CH3)
SCHEMATIC03/JTAG_TDO: CON12.13 R41.1 U39.4(CH3)
SCHEMATIC03/JTAG_TMS: CON12.7 R43.1 RP1.3(R2) U40.6(CH4)
SCHEMATIC03/N37: R202.1 SW7.16(B1)
SCHEMATIC03/N38: R40.1 SW7.15(B2)
SCHEMATIC03/N39: R201.1 SW7.14(B3)
SCHEMATIC03/N40: R39.1 SW7.13(B4)
SCHEMATIC03/N41: R233.1 SW7.12(B5)
SCHEMATIC03/N42: R38.1 SW7.11(B6)
SCHEMATIC03/N43: R37.1 SW7.10(B7)
SCHEMATIC03/N44: R36.1 SW7.9(B8)
SCHEMATIC03/N45: C221.2 CON12.4 CON12.6 CON12.8 CON12.10 CON12.11 CON12.12 CON12.14 CON12.16 CON12.18 CON12.20 L38.2
SCHEMATIC03/N122: R36.2 R37.2 R38.2 R39.2 R40.2 R188.1 R201.2 R202.2 R233.2
SCHEMATIC03/PG1: SW7.2(A2) U1.42(PG1/EPWM0_CH3/UART9_nRTS/UART6_TXD/I2C4_SCL/CAN2_TXD/EBI_nCS0/QEI0_B/TM1_EXT/RGMII1_PPS/RMII1_PPS/PowerOnSetting)
SCHEMATIC03/SWJ_nRESET: CON12.15 J3.2 U39.6(CH4)
SCHEMATIC04/C0_SCLK: C88.1 CON3.4 R46.2
SCHEMATIC04/CCAP0_DATA0: CON3.5 U1.70(PM2/CAN3_RXD/CCAP0_DATA0/EBI_AD5/EBI_ADR5)
SCHEMATIC04/CCAP0_DATA1: CON3.6 U1.71(PM3/CAN3_TXD/CCAP0_DATA1/EBI_AD6/EBI_ADR6)
SCHEMATIC04/CCAP0_DATA2: CON3.7 U1.72(PM4/I2C5_SDA/CCAP0_DATA2/EBI_AD7/EBI_ADR7)
SCHEMATIC04/CCAP0_DATA3: CON3.8 U1.73(PM5/I2C5_SCL/CCAP0_DATA3/EBI_AD8/EBI_ADR8)
SCHEMATIC04/CCAP0_DATA4: CON3.9 U1.74(PM6/CAN0_RXD/CCAP0_DATA4/EBI_AD9/EBI_ADR9)
SCHEMATIC04/CCAP0_DATA5: CON3.10 U1.75(PM7/CAN0_TXD/CCAP0_DATA5/EBI_AD10/EBI_ADR10)
SCHEMATIC04/CCAP0_DATA6: CON3.11 U1.77(PM8/I2C0_SDA/CCAP0_DATA6/EBI_AD11/EBI_ADR11)
SCHEMATIC04/CCAP0_DATA7: CON3.12 U1.78(PM9/I2C0_SCL/CCAP0_DATA7/EBI_AD12/EBI_ADR12)
SCHEMATIC04/CCAP0_DATA8: CON3.13 U1.79(PM10/EPWM1_CH2/CAN2_RXD/SPI3_SS0/CCAP0_DATA8/SPI2_I2SMCLK/EBI_AD13/EBI_ADR13)
SCHEMATIC04/CCAP0_DATA9: CON3.14 U1.80(PM11/EPWM1_CH3/CAN2_TXD/SPI3_SS1/CCAP0_DATA9/SPI2_SS1/EBI_AD14/EBI_ADR14)
SCHEMATIC04/CCAP0_HSYNC: CON3.16 U1.67(PK11/CAN1_TXD/CCAP0_HSYNC/EBI_AD2/EBI_ADR2)
SCHEMATIC04/CCAP0_nRST: CON3.18 U1.69(PM1/I2C4_SCL/SPI3_I2SMCLK/CCAP0_SFIELD/EBI_AD4/EBI_ADR4)
SCHEMATIC04/CCAP0_PIXCLK: CON3.3 U1.66(PK10/CAN1_RXD/CCAP0_PIXCLK/EBI_AD1/EBI_ADR1)
SCHEMATIC04/CCAP0_SCLK: R46.1 U1.65(PK9/I2C3_SCL/CCAP0_SCLK/EBI_AD0/EBI_ADR0)
SCHEMATIC04/CCAP0_VDD3V3: C90.2 C91.1 L18.1 U1.76(VDDIO2)
SCHEMATIC04/CCAP0_VSYNC: CON3.15 U1.68(PM0/I2C4_SDA/CCAP0_VSYNC/EBI_AD3/EBI_ADR3)
SCHEMATIC04/MVREF: C49.2 C58.1 R9.2 R14.1 U1.136(MVREF)
SCHEMATIC04/MZQ_PHY: R16.1 U1.134(MZQ_DDRPHY)
SCHEMATIC04/MZQ_SDRAM: R15.1 U1.133(MZQ_SDRAM)
SCHEMATIC05/AR_D0: NU3.1(D0) U1.116(PH12/UART14_nCTS/UART13_RXD/LCM_DATA20)
SCHEMATIC05/AR_D1: NU3.2(D1) U1.117(PH13/UART14_nRTS/UART13_TXD/LCM_DATA21)
SCHEMATIC05/AR_D10: NU4.3(D10) U1.91(PG8/EPWM1_CH4/UART12_RXD/CAN3_RXD/SPI2_SS0/LCM_VSYNC/LCM_MPU_RD/EN/I2C3_SDA/EBI_AD7/EBI_nCS0)
SCHEMATIC05/AR_D11: NU4.4(D11) U1.93(PG10/UART12_nRTS/UART13_TXD/SPI2_MOSI/LCM_CLK/EBI_AD9/EBI_nWRH)
SCHEMATIC05/AR_D12: NU4.5(D12) U1.94(PK4/UART12_nCTS/UART13_RXD/SPI2_MISO/LCM_DEN/LCM_MPU_RS/EBI_AD10/EBI_nWRL)
SCHEMATIC05/AR_D13: NU4.6(D13) U1.92(PG9/EPWM1_CH5/UART12_TXD/CAN3_TXD/SPI2_CLK/LCM_HSYNC/LCM_MPU_WR/RW/I2C3_SCL/EBI_AD8/EBI_nCS1)
SCHEMATIC05/CAN1_H: J2.1 R34.2 U7.7(CANH)
SCHEMATIC05/CAN1_L: J2.2 R34.1 U7.6(CANL)
SCHEMATIC05/GPIO5: CON4.29 U1.95(PI8/UART4_nCTS/UART3_RXD/LCM_DATA0/LCM_MPU_D0/EBI_AD11)
SCHEMATIC05/GPIO6: CON4.31 U1.96(PI9/UART4_nRTS/UART3_TXD/LCM_DATA1/LCM_MPU_D1/EBI_AD12)
SCHEMATIC05/GPIO12: CON4.32 U1.97(PI10/UART4_RXD/LCM_DATA2/LCM_MPU_D2/EBI_AD13)
SCHEMATIC05/GPIO13: CON4.33 U1.98(PI11/UART4_TXD/LCM_DATA3/LCM_MPU_D3/EBI_AD14)
SCHEMATIC05/GPIO14: CON4.8 U1.119(PH15/UART14_TXD/LCM_DATA23)
SCHEMATIC05/GPIO15: CON4.10 U1.118(PH14/UART14_RXD/LCM_DATA22)
SCHEMATIC05/GPIO16: CON4.36 U1.99(PI12/UART6_nCTS/UART5_RXD/LCM_DATA4/LCM_MPU_D4)
SCHEMATIC05/GPIO17: CON4.11 U1.100(PI13/UART6_nRTS/UART5_TXD/LCM_DATA5/LCM_MPU_D5)
SCHEMATIC05/GPIO22: CON4.15 U1.101(PI14/UART6_RXD/LCM_DATA6/LCM_MPU_D6)
SCHEMATIC05/GPIO23: CON4.16 U1.102(PI15/UART6_TXD/LCM_DATA7/LCM_MPU_D7)
SCHEMATIC05/GPIO24: CON4.18 U1.103(PH0/UART8_nCTS/UART7_RXD/LCM_DATA8/LCM_MPU_D8)
SCHEMATIC05/GPIO25: CON4.22 U1.104(PH1/UART8_nRTS/UART7_TXD/LCM_DATA9/LCM_MPU_D9)
SCHEMATIC05/GPIO26: CON4.37 U1.105(PH2/UART8_RXD/LCM_DATA10/LCM_MPU_D10)
SCHEMATIC05/GPIO27: CON4.13 U1.107(PH3/UART8_TXD/LCM_DATA11/LCM_MPU_D11)
SCHEMATIC05/N46: C83.1 C84.2 R261.2 R262.2 U7.3(VCC)
SCHEMATIC05/N47: R263.2 U7.8(STB)
SCHEMATIC05/N74: CB2.2 U8.1(C1+)
SCHEMATIC05/N75: CB3.2 U8.2(V+)
SCHEMATIC05/N76: CB2.1 U8.3(C1-)
SCHEMATIC05/N77: CB4.2 U8.4(C2+)
SCHEMATIC05/N78: CB4.1 U8.5(C2-)
SCHEMATIC05/N79: CB5.2 U8.6(V-)
SCHEMATIC05/N90: R50.2 R55.2
SCHEMATIC05/N109: J6.1 R51.2
SCHEMATIC05/N110: J6.2 R56.1
SCHEMATIC05/N121: C230.2 R264.1 U7.5(VIO)
SCHEMATIC05/PC13: R54.1 U1.113(PC13/UART12_nRTS/UART11_TXD/LCM_DATA17/LCM_MPU_D17) U9.2(\\\\RE) U9.3(DE)
SCHEMATIC05/PC14: U1.114(PC14/UART12_RXD/LCM_DATA18/LCM_MPU_CS) U9.1(RO)
SCHEMATIC05/PC15: U1.115(PC15/UART12_TXD/LCM_DATA19/LCM_MPU_TE/LCM_MPU_VSYNC) U9.4(DI)
SCHEMATIC05/PH4: U1.108(PH4/UART10_nCTS/UART9_RXD/LCM_DATA12/LCM_MPU_D12) U8.9(R2o)
SCHEMATIC05/PH5: U1.109(PH5/UART10_nRTS/UART9_TXD/LCM_DATA13/LCM_MPU_D13) U8.10(T2in)
SCHEMATIC05/PH6: U1.110(PH6/UART10_RXD/LCM_DATA14/LCM_MPU_D14) U8.12(R1o)
SCHEMATIC05/PH7: U1.111(PH7/UART10_TXD/LCM_DATA15/LCM_MPU_D15) U8.11(T1in)
SCHEMATIC05/RS485_A3_1: R49.1 R50.1 R51.1 U9.6(A)
SCHEMATIC05/RS485_B3_1: R55.1 R56.2 R57.1 U9.7(B)
SCHEMATIC05/UR10_CT: J5.3 U8.8(R2in)
SCHEMATIC05/UR10_RT: J5.4 U8.7(T2o)
SCHEMATIC05/UR10_RX: J5.2 U8.13(R1in)
SCHEMATIC05/UR10_TX: J5.1 U8.14(T1o)
SCHEMATIC05/VREF_VDD3V3: C95.1 L40.1 NU4.8(VREF)
SCHEMATIC06/N48: R65.2 U10.3(/Rst)
SCHEMATIC06/N49: T1.1 U12.38(PRE)
SCHEMATIC06/N50: T2.1 U12.6(R/B2)
SCHEMATIC06/N51: T3.1 U12.10(/CE2)
SCHEMATIC06/N52: R265.1 T4.1 U12.39(PSL)
SCHEMATIC06/PD0: R255.2 U1.122(PD0/UART3_nCTS/UART4_RXD/QSPI0_SS0)
SCHEMATIC06/PD1: R64.2 U1.123(PD1/UART3_nRTS/UART4_TXD/QSPI0_CLK)
SCHEMATIC06/PD2: R257.2 U1.124(PD2/UART3_RXD/QSPI0_MOSI0)
SCHEMATIC06/PD3: R258.2 U1.125(PD3/UART3_TXD/QSPI0_MISO0)
SCHEMATIC06/PD4: R259.2 U1.126(PD4/UART1_nCTS/UART2_RXD/I2C2_SDA/QSPI0_MOSI1)
SCHEMATIC06/PD5: R260.2 U1.127(PD5/UART1_nRTS/UART2_TXD/I2C2_SCL/QSPI0_MISO1)
SCHEMATIC06/QSPI0_CLK: C96.1 R64.1 R256.2
SCHEMATIC06/QSPI0_MISO0: R258.1 U10.8(Do/D1) U11.2(Do/D1)
SCHEMATIC06/QSPI0_MISO1: R62.1 R260.1 U10.1(Hld/D3) U11.7(Hld/D3)
SCHEMATIC06/QSPI0_MOSI0: R257.1 U10.15(Di/D0) U11.5(Di/D0)
SCHEMATIC06/QSPI0_MOSI1: R61.1 R259.1 U10.9(Wp/D2) U11.3(Wp/D2)
SCHEMATIC06/QSPI0_SS0: R63.1 R255.1 U10.7(CS) U11.1(/CS)
SCHEMATIC06/S_CLK: R256.1 U10.16(CLK) U11.6(CLK)
SCHEMATIC07/CLK: C104.1 R68.1 R230.2
SCHEMATIC07/N53: C110.1 R69.2 U25.1(/SHDN)
SCHEMATIC07/N54: Q9.2(SOURCE) R70.2 R71.1 U25.5(SET)
SCHEMATIC07/N55: Q9.3(DRAIN) R72.2
SCHEMATIC07/N56: D1.2 R74.2
SCHEMATIC07/N57: Q10.1(G) Q11.1(GATE) Q12.3(C) R75.2
SCHEMATIC07/N58: Q11.3(DRAIN) R76.2
SCHEMATIC07/N59: CON5.1(DAT2) R227.1
SCHEMATIC07/N60: CON5.2(DAT3) R228.1
SCHEMATIC07/N61: CON5.3(CMD) R229.1
SCHEMATIC07/N62: CON5.5(CLK) R230.1
SCHEMATIC07/N63: CON5.7(DAT0) R231.1
SCHEMATIC07/N64: CON5.8(DAT1) R232.1
SCHEMATIC07/N65: CON5.10(GND) CON5.11(GND) CON5.12(GND) CON5.13(GND) L24.2
SCHEMATIC07/N120: C112.1 R70.1 R72.1 R211.2 U25.4(VOUT)
SCHEMATIC07/PJ5: CON5.9(CD) R221.2 U1.83(PJ5/I2C3_SCL/SD1_nCD)
SCHEMATIC07/PJ6: R224.2 R229.2 U1.85(PJ6/CAN3_RXD/SD1_CMD/eMMC1_CMD)
SCHEMATIC07/PJ7: R68.2 U1.86(PJ7/CAN3_TXD/SD1_CLK/eMMC1_CLK)
SCHEMATIC07/PJ8: R223.2 R231.2 U1.87(PJ8/I2C4_SDA/SD1_DAT0/eMMC1_DAT0)
SCHEMATIC07/PJ9: R222.2 R232.2 U1.88(PJ9/I2C4_SCL/SD1_DAT1/eMMC1_DAT1)
SCHEMATIC07/PJ10: R226.2 R227.2 U1.89(PJ10/CAN0_RXD/SD1_DAT2/eMMC1_DAT2)
SCHEMATIC07/PJ11: R225.2 R228.2 U1.90(PJ11/CAN0_TXD/SD1_DAT3/eMMC1_DAT3)
SCHEMATIC07/SD1_VDD: C105.2 C106.1 L23.1 U1.84(VDDIO3)
SYSPWR_EN: R69.1 ; also on sheet 7

Not connected (* = marked no-connect by the designer): CON12 17* 19*; NU1 1(NC)* 8(VIN)*; U1 41(PA15/EPWM0_CH2/UART9_nCTS/UART6_RXD/I2C4_SDA/CAN2_RXD/EBI_ALE/QEI0_A/TM1/RGMII0_PPS/RMII0_PPS) 82(PJ4/I2C3_SDA/SD1_WP)*; U10 4(NC)* 5(NC)* 6(NC)* 11(NC)* 12(NC)* 13(NC)* 14(NC)*; U39 1(CH1)*; U40 1(CH1)*

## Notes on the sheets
sheet 9
- Power-on Setting
- L
- PG0
- Secure Boot
- Secure Boot Enable
- H
- Secure Boot Disable
- PG1
- Boot Source QSPI0, SD/eMMC I/O Voltage
- L
- 3.3V
- H
- 1.8V
- PG3
- PG2
- Boot Source
- L
- L
- QSPI0 Flash
- L
- H
- SD/eMMC
- H
- L
- NAND Flash
- H
- H
- USB
- PG7
- PG6
- Booting from QSPI0
- L
- L
- SPI-NAND, 1-bit
- H
- L
- SPI-NOR, 1-bit
- PG6
- Booting from SD/eMMC
- L
- SD0/eMMC0 booting
- H
- SD1/eMMC1 booting
- PG7
- Booting from SD/eMMC
- L
- eMMC 4-bit booting
- H
- eMMC 8-bit booting
- Internal pull-down
- L
- PG5
- L
- PG4
- Booting from NAND
- Ignore
- L
- PG4
- Booting from USB
- USBD booting
- L
- H
- NAND flash page 2KB
- H
- USBH booting
- H
- L
- NAND flash page 4KB
- H
- H
- NAND flash page 8KB
- PG5
- Booting from USBH
- L
- USBH port 0 booting
- PG7
- PG6
- Booting from NAND
- H
- USBH port 1 booting
- L
- L
- H
- L
- BCH T12
- Ignore
- PG6
- Booting from USBH
- H
- L
- BCH T24
- L
- Over-current low-active detect
- H
- H
- NO ECC
- H
- Over-current high-active detect
- Note: The GPIO PE15 (UART0_RXD) pin must be
  pulled to high level through an external resistor or
  an internal pull-up resistor in the external device
  (such as a transceiver or MCU).
- Note: The VDDIO1 is the input
  voltage of I/O group 1 and its
  voltage is 3.3V only.
- VDDIO1 (VDD3V3)
- 10K
- PE15
- SWJ Connector
- PG11~15 Connect to SWJ(I2S0)
sheet 10
- CCAP0 Connector
- Note: The VDDIO2 is the input voltage of I/O
  group 2 and its voltage is 1.8V ~ 3.3V. This
  voltage should be matched with the voltage of
  external connected device. (The default is
  3.3V on this board)
- Power
- DDR PHY
sheet 11
- CAN_1
- CAN_FD
- RS232_10
- Note: The VDDIO4 is the input voltage of I/O group 4
  and its voltage is 1.8V ~ 3.3V. This voltage should be
  matched with the voltage of external connected device.
  (The default is 3.3V on this board)
- RS485_12
- Raspberry Pi Connector
- Arduino UNO Connector
sheet 12
- QSPI0_Flash
- Note: The VDDIO5 is the input voltage of
  I/O group 5 and its voltage is 1.8V ~
  3.3V. This voltage should be matched with
  the voltage of external connected device.
  (The default is 1.8V on this board)
- NAND_Flash
- V2.3
sheet 13
- 3, Drain
- SI2301 (PMOS)
- For SD card compatibility
- 1, Gate
- 2, Source
- PN14 = L, VDD_SD OFF
- PN14 = H, VDD_SD ON
- Note: The VDDIO3 is the input voltage of I/O group 3
  and its voltage is 1.8V ~ 3.3V. This voltage should
  be matched with the voltage of external connected
  device. (The default is 3.3V but can be controlled by
  GPIO PN11 high or low state that follows the SD3.0
  timing on this board)
- nRESET = L, VDD_SD OFF
- nRESET = H, VDD_SD ON
- 3
  Collector
- 2N3904 (NPN)
- 1
  Base
- 2
  Emitter
- SD1
- VDD_SDIO
- SDIO (3.3V & 1.8V)
- 3, Drain
- PN11 = L, VDD_SDIO = 3.3V
- SI2302 (NMOS)
- Micro SD slot
- PN11 = H, VDD_SDIO = 1.8V
- 1, Gate
- 2, Source
